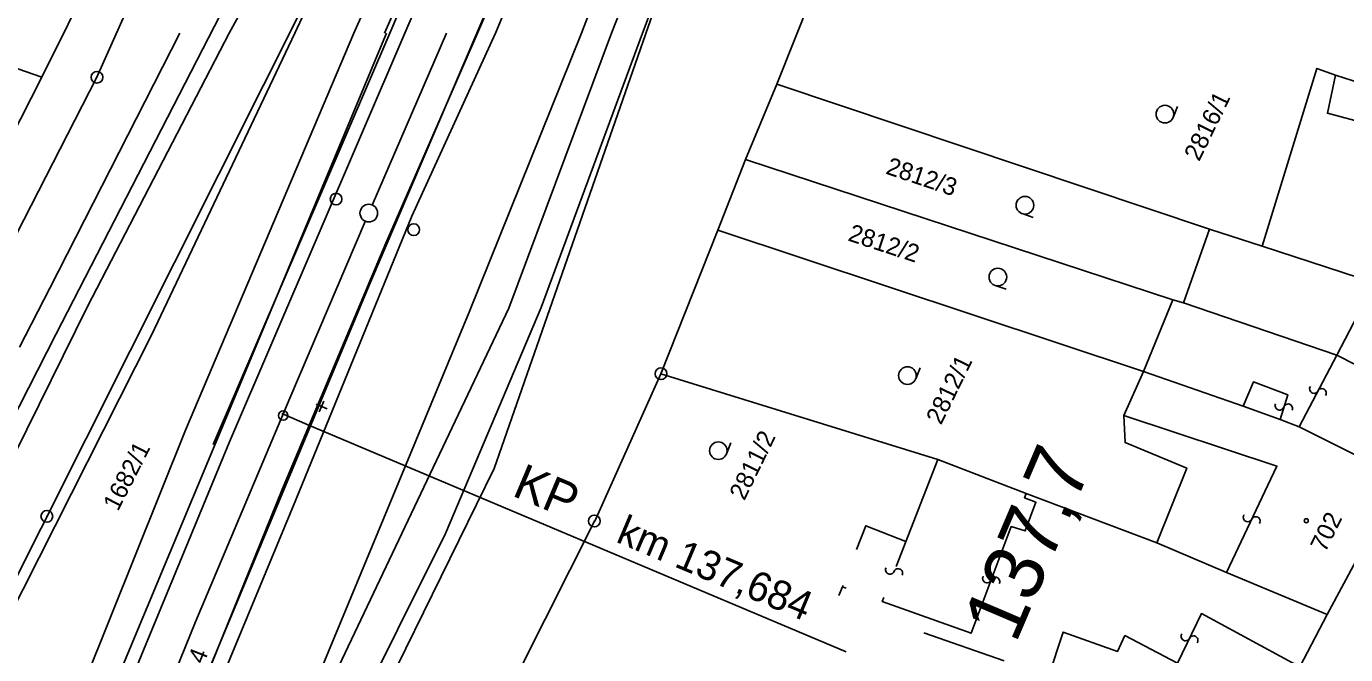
# Model space of a CAD drawing. Extents: x -658910 to -658078, y -1170373 to -1169331.
# Drawn here: x -658393.1 to -658281, y -1169852.8 to -1169799.4 of the extents above; entities that cross this region are included whole.
import ezdxf

# ---------------------------------------------------------------- set-up
doc = ezdxf.new("R2010")
doc.units = 0
for name, color, linetype in [('Vrstva 1', 7, 'Continuous'), ('Vrstva 10', 7, 'Continuous'), ('Vrstva 11', 7, 'Continuous'), ('Vrstva 12', 7, 'Continuous'), ('Vrstva 14', 7, 'Continuous'), ('Vrstva 16', 7, 'Continuous'), ('Vrstva 38', 7, 'Continuous'), ('Vrstva 39', 7, 'Continuous'), ('Vrstva 6', 7, 'Continuous'), ('Vrstva 7', 7, 'Continuous'), ('Vrstva 8', 7, 'Continuous'), ('Vrstva 9', 7, 'Continuous')]:
    doc.layers.add(name, color=color, linetype=linetype)

msp = doc.modelspace()

# ---------------------------------------------------------------- linework, layer by layer
at = {"layer": 'Vrstva 1'}
for p, q in [((-658321.969, -1169785.719), (-658329.34, -1169804.34)), ((-658387.14, -1169803.74), (-658387.04, -1169803.74)), ((-658387.14, -1169803.74), (-658387.04, -1169803.74)), ((-658329.34, -1169804.34), (-658332.012, -1169810.74)), ((-658334.352, -1169816.73), (-658332.012, -1169810.74)), ((-658334.352, -1169816.73), (-658339.18, -1169828.93)), ((-658339.18, -1169828.93), (-658344.79, -1169841.441))]:
    msp.add_line(p, q, dxfattribs=at)
for points in [[(-658387.09, -1169803.74), (-658379.66, -1169787.031), (-658371.41, -1169770.08), (-658363.031, -1169753.09), (-658350.949, -1169718.6), (-658329.91, -1169685.09), (-658309.48, -1169652.309), (-658298.289, -1169629.6), (-658291.762, -1169617.34), (-658282.25, -1169598.42), (-658273.73, -1169581.691), (-658253.98, -1169552.23), (-658232.398, -1169524.699), (-658206.289, -1169500.25)], [(-658535.25, -1169975.531), (-658525.109, -1169972.281), (-658506.949, -1169964.32), (-658490.84, -1169955.289), (-658479.949, -1169947.32), (-658468.961, -1169938.809), (-658451.859, -1169920.99), (-658433.102, -1169893.621), (-658430.531, -1169888.559), (-658387.09, -1169803.74)], [(-658344.84, -1169841.441), (-658351.121, -1169853.93), (-658358.621, -1169867.859), (-658367.191, -1169883.15), (-658382.238, -1169916.941), (-658391.102, -1169938.059), (-658392.09, -1169940.24)]]:
    msp.add_lwpolyline(points, dxfattribs=at)
msp.add_circle((-658387.09, -1169803.74), 0.499, dxfattribs=at)
msp.add_circle((-658387.09, -1169803.74), 0.499, dxfattribs=at)
at = {"layer": 'Vrstva 10'}
for points in [[(-658412.34, -1169868.25), (-658390.58, -1169825.61), (-658346.68, -1169740.23), (-658319.39, -1169686.96), (-658299.95, -1169648.82), (-658273.229, -1169598.35)], [(-658354.813, -1169800), (-658338.217, -1169761.133), (-658328.016, -1169737.523), (-658311.372, -1169701.327), (-658294.326, -1169669.378), (-658287.561, -1169657.031), (-658267.485, -1169620.8), (-658262.54, -1169612.307), (-658258.99, -1169605.547)], [(-658375.867, -1169800), (-658361.393, -1169773.644), (-658354.79, -1169760.67), (-658342.877, -1169737.984), (-658335.517, -1169720.03), (-658325.56, -1169701.303), (-658321.609, -1169695.48), (-658313.743, -1169679.786), (-658299.295, -1169651.229), (-658299.107, -1169647.523), (-658285.769, -1169623.061), (-658296.701, -1169647.814), (-658297.652, -1169652.866), (-658310.48, -1169681.38)], [(-658360.929, -1169800), (-658349.936, -1169774.389), (-658334.842, -1169739.91), (-658319.089, -1169701.899), (-658310.48, -1169681.38), (-658321.364, -1169701.87), (-658331.897, -1169722.678), (-658331.43, -1169723.306)], [(-658333.116, -1169726.471), (-658336.424, -1169738.132), (-658350.053, -1169771.475), (-658362.2, -1169800)], [(-658365.283, -1169800), (-658352.418, -1169771.155), (-658348.735, -1169762.183), (-658339.384, -1169737.033), (-658351.881, -1169761.731), (-658357.615, -1169772.947), (-658370.274, -1169800)], [(-658345.931, -1169800), (-658340.118, -1169784.754), (-658339.443, -1169780.485), (-658340.587, -1169778.372), (-658335.811, -1169761.813), (-658333.115, -1169751.576), (-658338.255, -1169764.06)], [(-658354.775, -1169800), (-658345.794, -1169779.212), (-658339.427, -1169764.497), (-658338.583, -1169764.847), (-658338.255, -1169764.06), (-658339.087, -1169763.754), (-658339.427, -1169764.497)], [(-658338.583, -1169764.847), (-658344.571, -1169779.21), (-658353.23, -1169800)], [(-658362.655, -1169800), (-658350.053, -1169771.475)], [(-658340.587, -1169778.372), (-658336.717, -1169779.987), (-658336.506, -1169781.479), (-658334.693, -1169783.861), (-658340.746, -1169800)], [(-658343.394, -1169800), (-658336.682, -1169782.957), (-658337.599, -1169782.361), (-658337.736, -1169781.012), (-658339.443, -1169780.485)], [(-658427.5, -1169951.109), (-658426.838, -1169944.052), (-658418.293, -1169924.085), (-658412.835, -1169905.664), (-658412.681, -1169899.985), (-658415.385, -1169894.759), (-658419.286, -1169891.437), (-658421.684, -1169889.994), (-658411.914, -1169872.007), (-658399.264, -1169846.174), (-658387.883, -1169823.23), (-658375.867, -1169800)], [(-658362.5, -1169799.992), (-658377.058, -1169834.921), (-658390.526, -1169867.22), (-658399.748, -1169892.989), (-658408.868, -1169924.83), (-658414.693, -1169947.06)], [(-658370.274, -1169800), (-658382.467, -1169825.639), (-658396.121, -1169852.622), (-658406.724, -1169877.812), (-658409.871, -1169887.316), (-658406.874, -1169893.983), (-658404.766, -1169900.848), (-658401.886, -1169890.78), (-658392.378, -1169865.645), (-658379.571, -1169833.72), (-658365.283, -1169800)], [(-658405.482, -1169935.482), (-658403.028, -1169926.019), (-658400.233, -1169916.097), (-658397.067, -1169905.522), (-658393.729, -1169895.606), (-658386.751, -1169876.773), (-658379.972, -1169859.803), (-658372.303, -1169841.365), (-658363.947, -1169821.339), (-658354.813, -1169800)], [(-658399.903, -1169892.997), (-658389.914, -1169868.81), (-658375.827, -1169834.718), (-658360.929, -1169800)], [(-658399.39, -1169913.576), (-658395.005, -1169899.698), (-658389.047, -1169882.978), (-658382.022, -1169865.114), (-658371.363, -1169838.762), (-658362.563, -1169817.838), (-658354.775, -1169800)], [(-658353.23, -1169800), (-658360.347, -1169815.55), (-658370.211, -1169839.636), (-658380.871, -1169865.378), (-658387.629, -1169882.876), (-658398.665, -1169913.79)], [(-658391.204, -1169912.074), (-658383.001, -1169889.369), (-658380.522, -1169884.732), (-658369.219, -1169856.817), (-658355.47, -1169823.699), (-658345.931, -1169800)], [(-658340.746, -1169800), (-658349.362, -1169823.293), (-658357.479, -1169842.49), (-658365.644, -1169858.872), (-658378.881, -1169885.997), (-658381.298, -1169889.443), (-658383.001, -1169889.369)], [(-658380.522, -1169884.732), (-658379.86, -1169885.098), (-658368.425, -1169857.701), (-658352.091, -1169823.348), (-658343.394, -1169800)], [(-658362.2, -1169800), (-658377.213, -1169834.929)]]:
    msp.add_lwpolyline(points, dxfattribs=at)
at = {"layer": 'Vrstva 12'}
for p, q in [((-658368.471, -1169831.522), (-658367.55, -1169831.909)), ((-658368.204, -1169832.176), (-658367.817, -1169831.255))]:
    msp.add_line(p, q, dxfattribs=at)
at = {"layer": 'Vrstva 14'}
msp.add_circle((-658366.777, -1169814.095), 0.5, dxfattribs=at)
at = {"layer": 'Vrstva 16'}
msp.add_circle((-658360.181, -1169816.693), 0.5, dxfattribs=at)
at = {"layer": 'Vrstva 38'}
msp.add_lwpolyline([(-658371.393, -1169832.311), (-658369.247, -1169833.228), (-658323.443, -1169852.546)], dxfattribs=at)
msp.add_circle((-658371.272, -1169832.481), 0.4, dxfattribs=at)
at = {"layer": 'Vrstva 6'}
for points in [[(-658380.039, -1169800), (-658391.086, -1169821.655), (-658393.686, -1169826.667)], [(-658363.705, -1169814.606), (-658357.396, -1169800)], [(-658370.721, -1169831.006), (-658364.298, -1169815.986)], [(-658394.353, -1169889.651), (-658388.744, -1169874.733), (-658378.733, -1169850.005), (-658370.721, -1169831.006)]]:
    msp.add_lwpolyline(points, dxfattribs=at)
msp.add_circle((-658363.998, -1169815.284), 0.75, dxfattribs=at)
at = {"layer": 'Vrstva 8'}
for p, q in [((-658422.339, -1169902.77), (-658366.591, -1169791.74)), ((-658329.34, -1169804.34), (-658292.59, -1169816.641)), ((-658295.699, -1169822.65), (-658332.012, -1169810.74)), ((-658292.59, -1169816.641), (-658288.102, -1169818.08)), ((-658288.102, -1169818.08), (-658278.559, -1169821.219)), ((-658294.781, -1169822.91), (-658295.699, -1169822.65)), ((-658281.77, -1169827.359), (-658294.781, -1169822.91)), ((-658273.289, -1169831.691), (-658281.77, -1169827.359)), ((-658339.23, -1169828.93), (-658339.13, -1169828.93)), ((-658339.23, -1169828.93), (-658339.13, -1169828.93)), ((-658353.359, -1169836.99), (-658390.5, -1169912.76)), ((-658391.398, -1169841.044), (-658391.298, -1169841.044)), ((-658344.89, -1169841.441), (-658344.79, -1169841.441))]:
    msp.add_line(p, q, dxfattribs=at)
for points in [[(-658436, -1169890.75), (-658426.172, -1169870.98), (-658406.578, -1169832.641), (-658400.809, -1169821.461), (-658391.77, -1169803.73), (-658382.809, -1169785.65), (-658474.191, -1169749.121)], [(-658485.32, -1169771.23), (-658391.77, -1169803.73)], [(-658333.641, -1169780.42), (-658353.359, -1169836.99)], [(-658281.891, -1169803.58), (-658283.461, -1169802.99), (-658288.102, -1169818.08)], [(-658277.48, -1169808.15), (-658282.559, -1169806.801), (-658281.891, -1169803.58), (-658278.34, -1169804.699)], [(-658334.352, -1169816.73), (-658298.191, -1169828.75), (-658289.711, -1169831.691), (-658286.59, -1169832.809), (-658284.961, -1169833.449), (-658273.711, -1169839.08), (-658270.449, -1169832.969)], [(-658292.59, -1169816.641), (-658294.781, -1169822.91)], [(-658284.961, -1169833.449), (-658281.77, -1169827.359), (-658278.559, -1169821.219)], [(-658295.699, -1169822.65), (-658298.191, -1169828.75)], [(-658319.208, -1169845.299), (-658315.648, -1169836.211), (-658339.18, -1169828.93)], [(-658299.871, -1169832.48), (-658298.191, -1169828.75)], [(-658289.711, -1169831.691), (-658288.852, -1169829.621), (-658285.93, -1169830.711), (-658286.59, -1169832.809)], [(-658282.578, -1169849.371), (-658291.148, -1169845.809), (-658286.852, -1169836.781), (-658299.871, -1169832.48), (-658299.75, -1169834.781), (-658294.512, -1169836.941), (-658297.051, -1169843.281), (-658308.16, -1169839.09), (-658308.309, -1169839.461), (-658307.328, -1169839.85), (-658308.23, -1169842.281), (-658309.43, -1169841.91), (-658312.82, -1169850.98), (-658320.379, -1169848.289), (-658320.243, -1169847.941)], [(-658308.16, -1169839.09), (-658315.648, -1169836.211)], [(-658276.289, -1169837.699), (-658282.578, -1169849.371), (-658284.91, -1169853.82), (-658293.27, -1169849.309), (-658295.289, -1169853.51), (-658299.762, -1169851.17), (-658300.398, -1169852.52), (-658305.02, -1169850.871), (-658307.531, -1169858.51), (-658302.801, -1169860.309), (-658301.941, -1169857.699), (-658300.82, -1169858.141), (-658300.43, -1169856.74), (-658297.602, -1169857.48), (-658302.121, -1169865.719), (-658293.68, -1169870.309), (-658289.23, -1169862.09), (-658297.602, -1169857.48)], [(-658322.557, -1169843.857), (-658321.789, -1169841.84), (-658318.379, -1169843.18)], [(-658291.148, -1169845.809), (-658297.051, -1169843.281)], [(-658324.084, -1169847.778), (-658323.762, -1169847.02), (-658323.445, -1169847.139)], [(-658323.762, -1169847.02), (-658323.723, -1169846.918)], [(-658310.02, -1169853.309), (-658316.851, -1169850.942)]]:
    msp.add_lwpolyline(points, dxfattribs=at)
for centre in [(-658339.18, -1169828.93), (-658339.18, -1169828.93), (-658391.348, -1169841.044), (-658344.84, -1169841.441)]:
    msp.add_circle(centre, 0.499, dxfattribs=at)
for centre, radius, start, end in [((-658283.702, -1169830.221), 0.376, 145.36582, 331.67695), ((-658283.037, -1169830.574), 0.377, 324.68977, 152.35299), ((-658286.627, -1169831.642), 0.376, 155.57644, 341.88757), ((-658285.91, -1169831.872), 0.377, 334.9004, 162.56361), ((-658289.338, -1169841.123), 0.376, 147.63152, 333.94266), ((-658288.659, -1169841.45), 0.377, 326.95548, 154.61869), ((-658319.727, -1169845.588), 0.376, 151.65311, 337.96424), ((-658319.028, -1169845.867), 0.377, 330.97707, 158.64028), ((-658311.48, -1169846.313), 0.376, 152.54744, 338.85857), ((-658310.776, -1169846.58), 0.377, 331.8714, 159.53461), ((-658294.618, -1169851.242), 0.376, 147.30442, 333.61555), ((-658293.941, -1169851.573), 0.377, 326.62838, 154.29159)]:
    msp.add_arc(centre, radius, start, end, dxfattribs=at)
at = {"layer": 'Vrstva 9'}
for p, q in [((-658295.673, -1169807.158), (-658295.3, -1169806.231)), ((-658308.5, -1169815.33), (-658307.551, -1169815.647)), ((-658310.801, -1169821.43), (-658309.852, -1169821.747)), ((-658317.542, -1169829.368), (-658317.174, -1169828.439)), ((-658333.608, -1169835.742), (-658333.24, -1169834.813))]:
    msp.add_line(p, q, dxfattribs=at)
for centre, radius in [((-658296.369, -1169806.878), 0.75), ((-658308.261, -1169814.618), 0.75), ((-658310.562, -1169820.718), 0.75), ((-658318.24, -1169829.092), 0.75), ((-658334.306, -1169835.466), 0.75), ((-658284.363, -1169841.419), 0.175)]:
    msp.add_circle(centre, radius, dxfattribs=at)

# ---------------------------------------------------------------- texts
at = {"layer": 'Vrstva 11'}
for s, rotation, p in [('1682/1', 62.98075, (-658385.306, -1169840.673)), ('0,4', 68.55443, (-658378.628, -1169855.232))]:
    msp.add_text(s, height=1.5, rotation=rotation, dxfattribs=at).set_placement(p)
at = {"layer": 'Vrstva 39'}
for s, height, p in [('KP', 3, (-658351.921, -1169839.255)), ('km 137,684', 2.5, (-658343.102, -1169843.18))]:
    msp.add_text(s, height=height, rotation=337.13237, dxfattribs=at).set_placement(p)
at = {"layer": 'Vrstva 7'}
msp.add_text('137,7', height=4.999, rotation=66.89243, dxfattribs=at).set_placement((-658309.061, -1169851.947))
at = {"layer": 'Vrstva 9'}
for s, rotation, p in [('2816/1', 63.88515, (-658293.465, -1169810.954)), ('2812/3', 341.49384, (-658320.16, -1169811.92)), ('2812/2', 341.90208, (-658323.371, -1169817.6)), ('2812/1', 63.88515, (-658315.389, -1169833.343)), ('2811/2', 63.88515, (-658332.098, -1169839.765)), ('702', 63.88515, (-658282.745, -1169844.178))]:
    msp.add_text(s, height=1.5, rotation=rotation, dxfattribs=at).set_placement(p)

doc.saveas('drawing.dxf')
